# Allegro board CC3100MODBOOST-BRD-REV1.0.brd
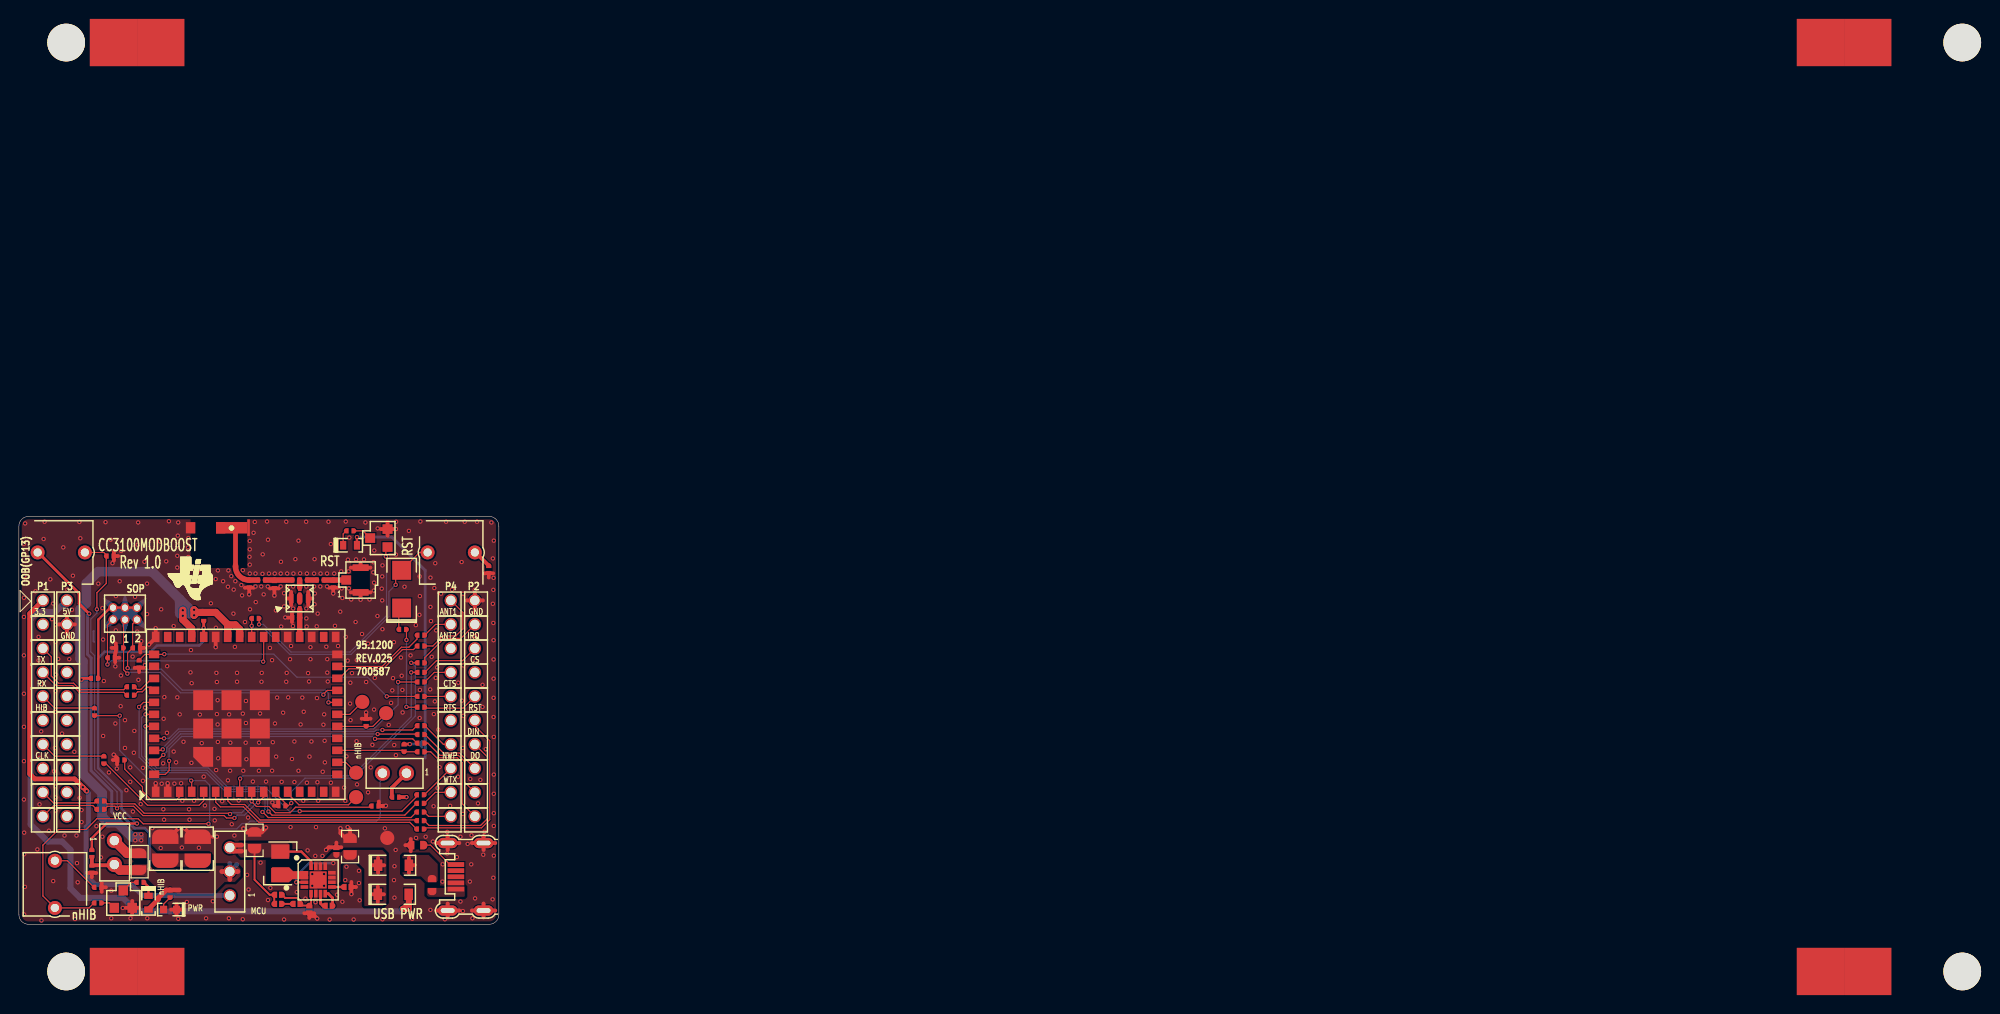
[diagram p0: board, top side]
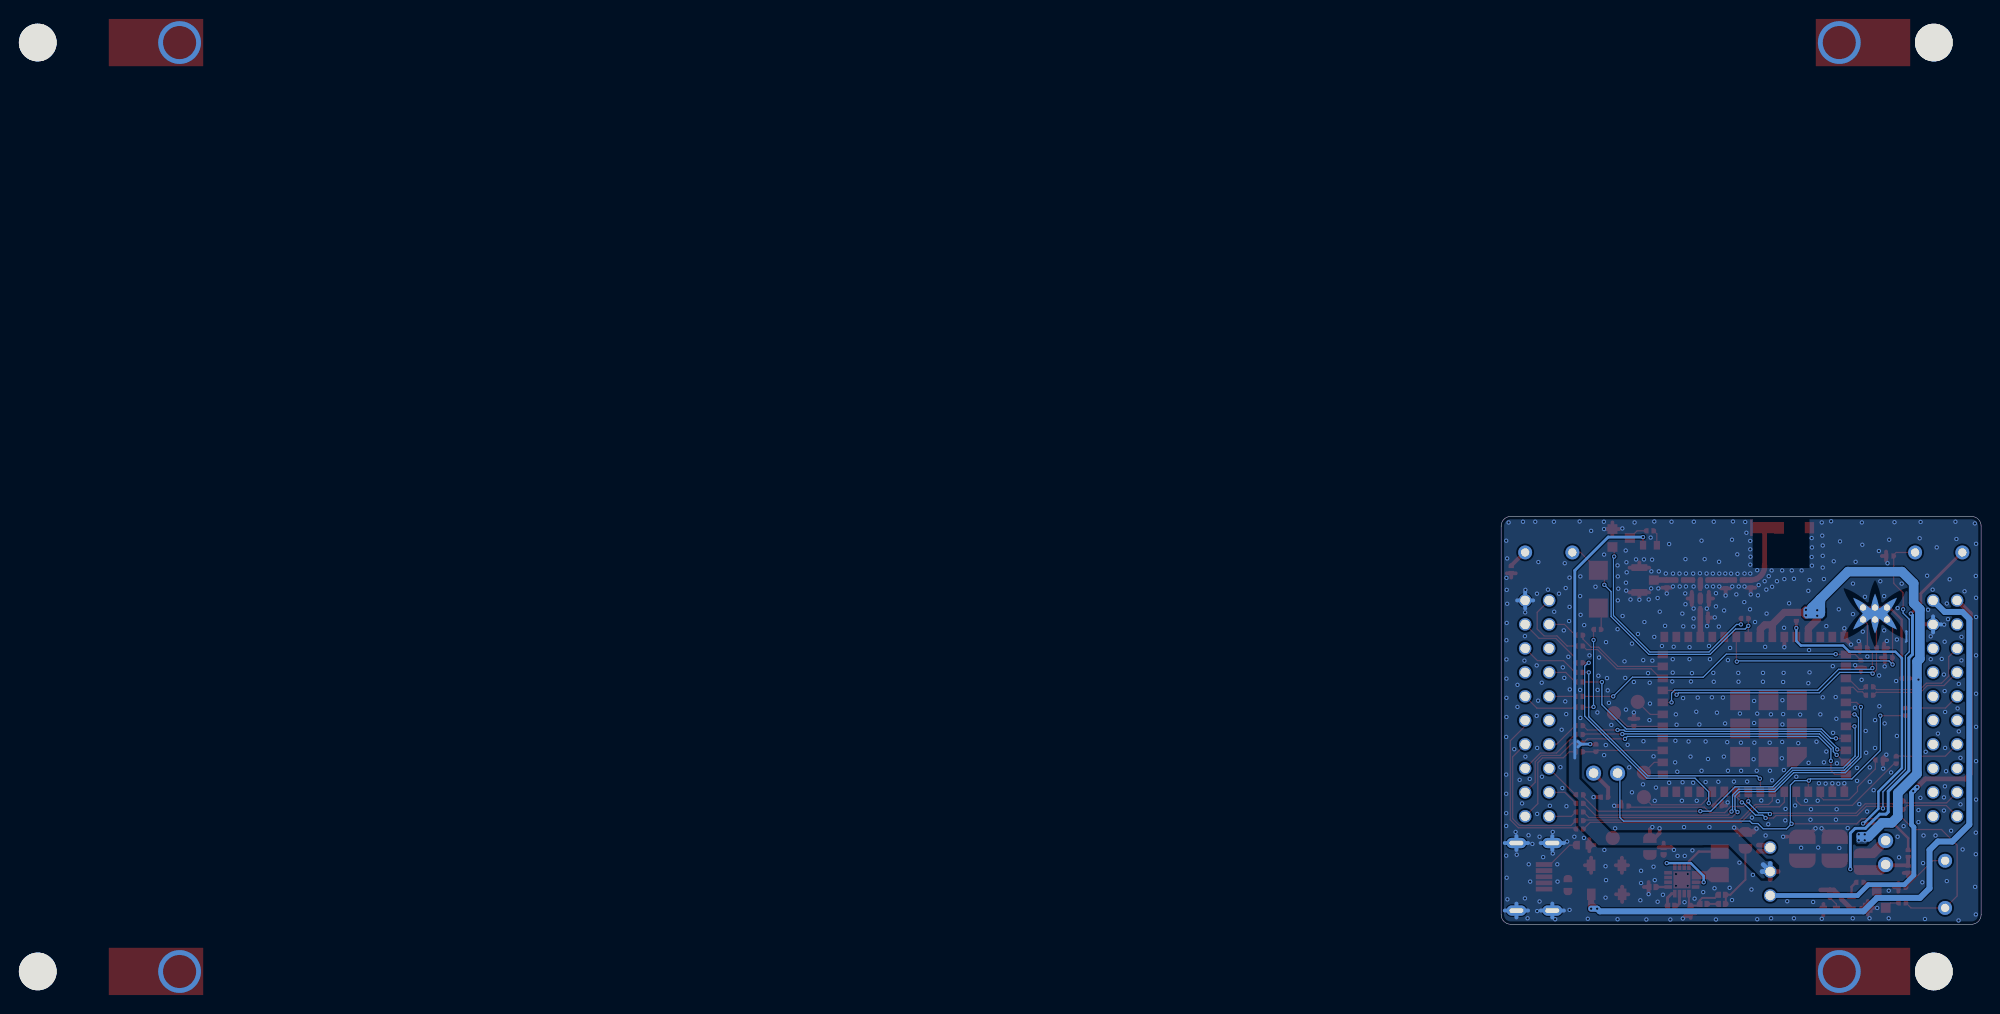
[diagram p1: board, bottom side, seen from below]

Outline 50.8 x 43.18 mm; copper layers: TOP, BOTTOM. Coordinates in mm from the lower left corner of the outline.
Outline path: 0,42.16 0,1.02 arc(0.3,0.3) 1.02,0 49.78,0 arc(50.5,0.3) 50.8,1.02 50.8,42.16 arc(50.5,42.88) 49.78,43.18 1.02,43.18 arc(0.3,42.88) 0,42.16

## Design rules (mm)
net group RF-50: nets N16994724 N16994729 N16994739 N17016892

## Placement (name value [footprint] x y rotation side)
ANT1  2.4GHz  [ANT-T77H533_00C]  19.77 41.98 0 top
C3  10nF  [YT-C-0402]  32.79 1.96 270 top
C4  22uF  [C-0805]  24.94 8.89 180 top
C7  10nF  [YT-C-0402]  34.79 3.95 90 top
C15  0.1uF  [YT-C-0402]  33.6 7.75 180 top
C17  2.2uF  [C-0805]  35.05 8.23 180 top
C23  22pF  [YT-C-0402]  27.43 3.13 90 top
C47  1uF  [C-0402S0]  7.72 5.84 180 top
C64  1.0pF  [C-0402S0]  24.38 36.04 0 top
C65  100uF  [C-1210]  15.49 8 0 top
C66  100uF  [C-1210]  18.92 8 0 top
C67  10pF  [C-0402S0]  31.9 36.45 270 top
C68  DNP  [C-0402S0]  27.04 35.97 0 top
D1  LED-Y  [LD-0603A]  35.05 40.13 270 top
D3  MBR130T1G  [SOD-123A]  39.65 6.25 270 top
D4  MBR130T1G  [SOD-123A]  39.62 3.17 270 top
D5  LED  [LD-0603S0]  16 1.56 90 top
D6  LED-G  [LD-0603A]  13.72 2.29 180 top
D8  DIODE SCHOTTKY  [M-D-SMAH2_3]  40.51 35.48 0 top
FB17  60R  [L-0603S0]  43.73 4.15 0 top
FB18  60R  [L-0603S0]  42.16 8.38 270 top
J2  CONN_U.FL  [CJ-RF-S3_1X3-3]  36.17 36.45 270 top
J3  MM8030-2610RJ3  [CN-MM8030S0]  29.72 34.49 0 top
J4  DNP  [CN-D3X2-1_27HD]  11.23 32.89 270 top
J5  jumper  [CN-2X1-2_54S0]  39.75 16 180 top
J6  jumper  [CN-2X1-2_54S0]  10.11 7.59 270 top
J7  SUA-160M3B-L2E-TR1  [CJ-USBSUA-160M3B-L2AT]  48.13 5.03 90 top
J8  CON3X1  [CN-3X1-2_54]  22.33 5.59 90 top
J9  Header Male 2x10  [CN-10X2-2_54C]  46.99 22.86 270 bottom
J10  Header Male 2x10  [CN-10X2-2_54C]  3.81 22.86 270 bottom
L1  1uH  [L-S3X3A]  27.66 6.45 0 top
L4  3.6nH  [L-0402S0]  25.68 36.45 90 top
L6  DNP  [L-0402S0]  33.27 36.04 180 top
L9  DNP  [L-0402S0]  29.31 32.47 90 top
NOREF  -  [unnamed]  0 88.35 90 top
NOREF#2  -  [#2]  1.6 0 90 top
NOREF#3  -  [#2]  50.8 1.02 0 top
NOREF#4  -  [#2]  117.86 91.86 90 top
NOREF#5  -  [#2]  92.86 96.86 0 top
NOREF#6  -  [unnamed#3]  210.7 88.35 90 top
NOREF#7  -  [unnamed#4]  210.7 0.01 90 top
NOREF#8  -  [#2]  0 42.16 0 top
NOREF#9  -  [#2]  12.01 -0.5 0 top
NOREF#10  -  [#2]  1.02 43.18 90 top
NOREF#11  -  [#2]  1.02 0 90 top
NOREF#12  -  [#2]  1.02 88.36 90 top
NOREF#13  -  [unnamed#5]  0 0.01 90 top
NOREF#14  -  [#2]  0 42.16 0 top
NOREF#15  -  [#2]  1.02 0 90 top
NOREF#16  -  [#2]  0 1.02 0 top
NOREF#17  -  [#2]  1.02 88.36 90 top
NOREF#18  -  [#2]  5 -10 90 top
Q7  BSS138LT3G  [SOT-23B]  11.05 2.67 270 top
Q8  BSS138LT3G  [SOT-23B]  38.1 40.89 0 top
R4  100k  [R-0402S0]  9.78 28.22 270 top
R5  430K  [YT-C-0402]  29.39 2.16 270 top
R7  100k  [R-0402S0]  10.67 29.26 90 top
R8  10k  [R-0402S0]  12.45 29.26 270 top
R9  1k  [R-0402S0]  8 26.04 270 top
R10  DNP  [R-0402S0]  40.61 31.22 270 top
R12  100R  [R-0402S0]  8.36 3.91 270 top
R13  150K  [YT-C-0402]  30.74 1.57 180 top
R14  100R  [R-0402S0]  49.73 37.57 180 top
R15  0R  [R-0402S0]  7.72 7.49 180 top
R16  DNP  [R-0402S0]  19.56 32.49 0 top
R20  1K  [R-0402S0]  8 22.49 0 top
R21  39K  [YT-C-0402]  27.43 2.16 270 top
R22  0R  [R-0402S0]  8.99 17.4 0 top
R24  DNP  [R-0402S0]  8.64 13.06 90 top
R25  DNP  [R-0402S0]  8.64 12.17 90 top
R26  DNP  [R-0402S0]  42.55 29.46 270 top
R27  DNP  [R-0402S0]  42.55 30.61 270 top
R29  0R  [R-0402S0]  42.55 25.65 270 top
R36  0R  [R-0402S0]  42.55 24.13 270 top
R37  0R  [R-0402S0]  42.55 21.03 270 top
R38  0R  [R-0402S0]  42.49 13.72 270 top
R39  DNP  [R-0402S0]  42.49 12.8 270 top
R40  DNP  [R-0402S0]  42.49 11.89 270 top
R44  0R  [R-0402S0]  42.55 27.69 90 top
R46  0R  [R-0402S0]  42.55 26.67 90 top
R48  0R  [R-0402S0]  42.55 22.99 90 top
R65  0R  [R-0402S0]  42.49 10.08 90 top
R66  0R  [R-0402S0]  42.49 10.97 90 top
R67  DNP  [R-0402S0]  42.55 20.09 90 top
R68  DNP  [R-0402S0]  42.55 19.18 90 top
R71  270  [R-0402S0]  12.83 4.45 90 top
R72  270  [R-0402S0]  35.05 41.66 270 top
R73  0R  [R-0402S0]  29.31 36.45 90 top
R74  DNP  [R-0402S0]  30.12 36.45 90 top
R75  DNP  [R-0402S0]  10.79 17.4 270 top
R76  DNP  [R-0201S1]  29.72 35.2 0 top
R77  33k  [R-0402S0]  9.65 38.99 270 top
R78  3.3K  [R-0402S0]  27.84 12.55 90 top
R79  DNP  [R-0201S1]  29.72 33.78 180 top
R81  0R  [R-0402S0]  11.81 25.15 90 top
R82  0R  [R-0402S0]  11.81 24.26 90 top
R83  DNP  [R-0402S0]  42.55 18.26 90 top
R84  33k  [R-0402S0]  37.69 12.52 270 top
R94  DNP  [R-0805]  12.78 6.63 0 top
R111  DNP  [R-0402S0]  40.77 18.67 0 top
R112  100K  [R-0402S0]  36.75 21.36 180 top
R113  100K  [R-0402S0]  12.73 27.56 0 top
R114  10K  [R-0402S0]  39.88 13.46 270 top
R205  330R  [R-0402S0]  16 3.23 180 top
R209  10k  [R-0402S0]  8.36 2.26 270 top
R210  10k  [R-0402S0]  25.02 32.38 270 top
SW1  1BT002-0120L  [SW-D6_2X6_2-2]  4.49 39.37 180 top
SW2  1BT002-0120L  [SW-D6_2X6_2-2]  45.76 39.37 180 top
SW3  1BT002-0120L  [SW-D6_2X6_2-2]  3.81 4.23 270 top
TP1  TP SMD  [ICT059]  38.99 9.14 0 top
TP2  TP SMD  [ICT059]  35.69 13.46 0 top
TP3  TP SMD  [ICT059]  35.69 16.05 0 top
TP4  TP SMD  [ICT059]  38.86 22.35 0 top
TP5  TP SMD  [ICT059]  36.35 23.55 0 top
U1  TLV62090  [TQFN-3X3-16ESHS2]  31.67 4.7 270 top
U11  TI CC3100 module  [E-PMODULE-S20_5X17_5-54S]  24 22.23 0 top

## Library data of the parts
ANT1 = ANT-T77H533_00C
C3 C7 C15 C23 R5 R13 R21 = YT-C-0402
C4 C17 = C-0805
C47 C64 C67 C68 = C-0402S0
C65 C66 = C-1210
D1 D6 = LD-0603A
D3 D4 = SOD-123A
D5 = LD-0603S0
D8 = M-D-SMAH2_3
FB17 FB18 = L-0603S0
J2 = CJ-RF-S3_1X3-3
J3 = CN-MM8030S0
J4 = CN-D3X2-1_27HD
J5 J6 = CN-2X1-2_54S0
J7 = CJ-USBSUA-160M3B-L2AT
J8 = CN-3X1-2_54
J9 J10 = CN-10X2-2_54C
L1 = L-S3X3A
L4 L6 L9 = L-0402S0
Q7 Q8 = SOT-23B
R4 R7-R10 R12 R14-R16 R20 R22 R24-R27 R29 R36-R40 R44 R46 R48 R65-R68 R71-R75 R77 R78 R81-R84 R111-R114 R205 R209 R210 = R-0402S0
R76 R79 = R-0201S1
R94 = R-0805
SW1-SW3 = SW-D6_2X6_2-2
TP1-TP5 = ICT059
U1 = TQFN-3X3-16ESHS2
U11 = E-PMODULE-S20_5X17_5-54S

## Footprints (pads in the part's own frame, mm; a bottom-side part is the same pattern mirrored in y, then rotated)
ANT-T77H533_00C
  rect 0.406x0.406 smd: 1(3.163,-4.005)
  rect 0.991x1.194 smd: 2(1.595,0) 3(-1.595,0)
C-0402S0
  custom 0.127x0.127 smd: 1(0,-0.406) 2(0,0.406)
C-0805
  custom 0.254x0.254 smd: 1(0,-0.889) 2(0,0.889)
C-1210
  custom 0.381x0.381 smd: 1(0,-1.27) 2(0,1.27)
CJ-RF-S3_1X3-3
  rect 0.991x1.041 smd: 1(0,-1.524)
  rect 0.711x1.702 smd: 2(1.311,0) 3(-1.311,0)
CJ-USBSUA-160M3B-L2AT
  rect 0.508x1.753 smd: 1(-1.3,1.877) 2(-0.65,1.877) 3(0,1.877) 4(0.65,1.877) 5(1.3,1.877)
  oval 1.092x2.083 hole 0.483x1.473: S1(3.575,-1.05) S2(-3.575,-1.05) S3(3.575,2.75) S4(-3.575,2.75)
CN-2X1-2_54S0
  round 1.6 hole 0.991: 1(-1.27,0) 2(1.27,0)
CN-3X1-2_54
  round 1.321 hole 0.991: 1(-2.54,0) 2(0,0) 3(2.54,0)
CN-10X2-2_54C
  round 1.321 hole 0.991: 1(-11.43,-1.27) 2(-11.43,1.27) 3(-8.89,-1.27) 4(-8.89,1.27) 5(-6.35,-1.27) 6(-6.35,1.27) 7(-3.81,-1.27) 8(-3.81,1.27) 9(-1.27,-1.27) 10(-1.27,1.27) 11(1.27,-1.27) 12(1.27,1.27) 13(3.81,-1.27) 14(3.81,1.27) 15(6.35,-1.27) 16(6.35,1.27) 17(8.89,-1.27) 18(8.89,1.27) 19(11.43,-1.27) 20(11.43,1.27)
CN-D3X2-1_27HD
  round 0.965 hole 0.66: 1(0.635,-1.27) 2(-0.635,-1.27) 3(0.635,0) 4(-0.635,0) 5(0.635,1.27) 6(-0.635,1.27)
CN-MM8030S0
  rect 0.356x0.356 smd: 1(0,-0.978) 4(0,0.978)
  rect 0.508x1.016 smd: 2(-0.904,0) 3(0.904,0)
E-PMODULE-S20_5X17_5-54S
  rect 0.813x1.092 smd: 1(-9.525,-8.196) 2(-8.255,-8.196) 3(-6.985,-8.196) 4(-5.715,-8.196) 5(-4.445,-8.196) 6(-3.175,-8.196) 7(-1.905,-8.196) 8(-0.635,-8.196) 9(0.635,-8.196) 10(1.905,-8.196) 11(3.175,-8.196) 12(4.445,-8.196) 13(5.715,-8.196) 14(6.985,-8.196) 15(8.255,-8.196) 16(9.525,-8.196) 28(9.525,8.196) 29(8.255,8.196) 30(6.985,8.196) 31(5.715,8.196) 32(4.445,8.196) 33(3.175,8.196) 34(1.905,8.196) 35(0.635,8.196) 36(-0.635,8.196) 37(-1.905,8.196) 38(-3.175,8.196) 39(-4.445,8.196) 40(-5.715,8.196) 41(-6.985,8.196) 42(-8.255,8.196) 43(-9.525,8.196)
  rect 1.092x0.813 smd: 17(9.696,-6.35) 18(9.696,-5.08) 19(9.696,-3.81) 20(9.696,-2.54) 21(9.696,-1.27) 22(9.696,0) 23(9.696,1.27) 24(9.696,2.54) 25(9.696,3.81) 26(9.696,5.08) 27(9.696,6.35) 44(-9.696,6.35) 45(-9.696,5.08) 46(-9.696,3.81) 47(-9.696,2.54) 48(-9.696,1.27) 49(-9.696,0) 50(-9.696,-1.27) 51(-9.696,-2.54) 52(-9.696,-3.81) 53(-9.696,-5.08) 54(-9.696,-6.35)
  custom 0.527x0.527 smd: 55(-4.5,-4.5)
  rect 2.108x2.108 smd: 56(-1.5,-4.5) 57(1.5,-4.5) 58(-4.5,-1.5) 59(-1.5,-1.5) 60(1.5,-1.5) 61(-4.5,1.5) 62(-1.5,1.5) 63(1.5,1.5)
ICT059
  round 1.499 smd: 1(0,0)
L-0402S0
  custom 0.127x0.127 smd: 1(0,-0.406) 2(0,0.406)
L-0603S0
  custom 0.191x0.191 smd: 1(0,-0.686) 2(0,0.686)
L-S3X3A
  rect 1.905x1.524 smd: 1(0,-1.246) 2(0,1.246)
LD-0603A
  rect 0.914x0.66 smd: 1(0,0.728) 2(0,-0.728)
LD-0603S0
  rect 0.813x0.762 smd: 1(0,0.686) 2(0,-0.686)
M-D-SMAH2_3
  rect 2.007x2.007 smd: 1(0,1.999) 2(0,-1.999)
R-0201S1
  custom 0.076x0.076 smd: 1(0,-0.229) 2(0,0.229)
R-0402S0
  custom 0.127x0.127 smd: 1(0,-0.406) 2(0,0.406)
R-0805
  custom 0.254x0.254 smd: 1(0,-0.889) 2(0,0.889)
SOD-123A
  rect 1.219x0.914 smd: 1(0,-1.633) 2(0,1.633)
SOT-23B
  rect 1.067x1.016 smd: 1(0.92,-0.951) 2(0.92,0.951) 3(-0.921,0)
SW-D6_2X6_2-2
  round 1.473 hole 0.864: T1(-2.5,0) T2(2.5,0)
TQFN-3X3-16ESHS2
  rect 0.381x0.813 smd: 1(-0.75,-1.455) 2(-0.25,-1.455) 3(0.25,-1.455) 4(0.75,-1.455) 9(0.75,1.455) 10(0.25,1.455) 11(-0.25,1.455) 12(-0.75,1.455)
  rect 0.813x0.381 smd: 5(1.455,-0.75) 6(1.455,-0.25) 7(1.455,0.25) 8(1.455,0.75) 13(-1.455,0.75) 14(-1.455,0.25) 15(-1.455,-0.25) 16(-1.455,-0.75)
  rect 1.803x1.803 smd: 17(0,0)
unnamed
  round 3.988 hole 3.988 unplated: (5.004,-5.004)
  rect 5.004x5.004 smd: (5.004,-10.008) (5.004,-15.011)
  round 1.016 smd: (5.004,-15.011) 1(5.004,-10.008)
unnamed#3
  round 1.016 smd: (5.006,20.018) 1(5.006,15.014)
  rect 5.004x5.004 smd: (5.006,20.018) (5.006,15.014)
  round 3.988 hole 3.988 unplated: (5.006,5.006)
unnamed#4
  round 1.016 smd: (-5.001,20.018) 1(-5.001,15.014)
  rect 5.004x5.004 smd: (-5.001,20.018) (-5.001,15.014)
  round 3.988 hole 3.988 unplated: (-5.001,5.006)
unnamed#5
  round 3.988 hole 3.988 unplated: (-5.004,-5.004)
  rect 5.004x5.004 smd: (-5.004,-10.008) (-5.004,-15.011)
  round 1.016 smd: (-5.004,-15.011) 1(-5.004,-10.008)
YT-C-0402
  custom 0.153x0.153 smd: 1(0,-0.406) 2(0,0.406)

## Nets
GND: ANT1.2 ANT1.3 C4.1 C7.1 C15.1 C17.1 C47.2 C64.1 C65.2 C66.2 C68.1 D5.2 FB18.1 J2.2 J2.3 J3.2 J3.3 J7.S1 J7.S2 J7.S3 J7.S4 J9.1 J10.3 L6.2 L9.2 Q7.2 Q8.2 R4.2 R7.2 R8.2 R12.2 R13.2 R14.2 R75.1 R77.2 R78.2 R84.2 R112.1 R113.1 TP1.1 U1.6 U1.14 U1.15 U1.17 U11.1 U11.2 U11.16 U11.27 U11.28 U11.30 U11.32 U11.38 U11.43 U11.55 U11.56 U11.57 U11.58 U11.59 U11.60 U11.61 U11.62 U11.63
VCC_3V3: C47.1 D1.1 D6.1 J6.2 J8.2 R15.2 R94.1 R111.2 R114.2 R205.1 SW1.T2
VCC_5V: C15.2 C17.2 D3.1 D4.1 U1.3 U1.10 U1.11 U1.12 U1.13
VCC_HOST_3V3: J8.1 J10.2
VCC_MCU_5V: D4.2 J10.1
VDD_FLASH: R15.1 R16.1 U11.39
ANT_SEL_1: R26.1 U11.25
ANT_SEL_2: R27.1 U11.26
CC_GPIO08: R67.2 U11.53
CC_GPIO09: R68.2 U11.54
CC_GPIO12: R24.1 R84.1 U11.9
CC_GPIO13: R25.1 R77.1 SW1.T1 U11.10
CC_IRQ: R44.2 R78.1 U11.11
CC_MODESEL: R83.2 R111.1 U11.19
CC_NHIB: J5.2 R20.1 R209.1 SW3.T2 U11.4
CC_NWP_UART_TX: R37.1 U11.52
CC_SPI_CLK: R22.1 U11.5
CC_SPI_CS: R46.2 U11.8
CC_SPI_DIN: R65.2 U11.6
CC_SPI_DOUT: R66.2 U11.7
CC_UART1_CTS: R29.1 U11.51
CC_UART1_RTS: R36.1 R113.2 U11.44
CC_UART1_RX: R82.1 U11.47
CC_UART1_TX: R81.1 U11.46
CC_VBAT: C65.1 C66.1 J6.1 R9.1 R16.2 R94.2 U11.36 U11.37 U11.40
CC_WL_RS232_RX: R39.1 U11.49
CC_WL_RS232_TX: R40.1 U11.48
CC_WL_UART_TX: R38.1 U11.50
MCU_RESET: R10.2 R48.2
REG_3V3: C4.2 C23.2 J8.3 L1.2 R21.1 U1.16
RESET_N: D8.1 R210.1 SW2.T2 U11.35
SOP0: J4.1 R4.1 U11.34
SOP1: J4.3 R7.1 U11.24
SOP2/TCXO_EN: J4.5 R8.1 U11.23
N16764527: J10.6 R81.2
N16764535: J10.8 R82.2
N16791492: R75.2 U11.3
N16793910: J3.1 L9.1 R79.2 U11.31
N16834605: J10.10 R20.2
N16837569: J4.2 J4.4 J4.6 R9.2
N16839855: J10.14 R22.2
N16840001: J10.18 R24.2
N16840004: J10.20 R25.2
N16841033: J9.2 R26.2
N16841054: J9.4 R27.2
N16841184: J9.8 R29.2
N16841224: J9.10 R36.2
N16841243: J9.14 R37.2
N16841270: J9.16 R38.2
N16841340: J9.18 R39.2
N16841345: J9.20 R40.2
N16842182: J9.3 R44.1
N16842199: J9.5 R46.1
N16842274: J9.9 R48.1
N16842295: J9.11 R65.1
N16842317: J9.13 R66.1
N16842351: J9.15 R67.1
N16842362: J9.17 R68.1
N16842381: J9.19 R83.1
N16884236: D8.2 R10.1
N16888596: FB17.1 J7.1
N16892431: D5.1 R205.2
N16917012: D3.2 FB17.2
N16970552: C7.2 U1.9
N16970558: C23.1 R5.2 R13.1 U1.5
N16970663: C3.1 U1.7
N16970665: C3.2 U1.8
N16970679: L1.1 U1.1 U1.2
N16970748: R5.1 R21.2
N16976507: Q7.1 R209.2
N16976519: D6.2 R71.1
N16976522: Q7.3 R71.2
N16976578: D1.2 R72.1
N16976580: Q8.3 R72.2
N16976712: Q8.1 R210.2
N16994679: J3.4 R73.1 R74.2 R76.2
N16994724: C67.1 R74.1
N16994729: C67.2 J2.1 L6.1
N16994739: C68.2 L4.1 R73.2
N17016892: ANT1.1 C64.2 L4.2
N17029182: R76.1 R79.1
N17031765: R12.1 SW3.T1
N17035781: J5.1 R114.1
N17040721: R112.2 TP4.1 U11.21
N17042673: R14.1 SW2.T1
N17042921: FB18.2 J7.5
N17042983: TP2.1 U11.12
N17042994: TP3.1 U11.18
N17043038: TP5.1 U11.22

Pads without a net: J7 2 3 4; J9 6 7 12; J10 4 5 7 9 11 12 13 15 16 17 19; NOREF 1; NOREF#6 1; NOREF#7 1; NOREF#13 1; U1 4; U11 13 14 15 17 20 29 33 41 42 45

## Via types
v1: diameter 0.457, hole 0.254, TOP to BOTTOM, 592 vias
v2: diameter 0.254, hole 0.254, TOP to BOTTOM, 4 vias

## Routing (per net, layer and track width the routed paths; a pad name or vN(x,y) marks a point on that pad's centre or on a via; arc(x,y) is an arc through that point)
GND: length 108.9
  TOP w0.406: v1(16.89,10.16) 16,9.27 C65.2 ; v1(32.51,7.87) 32.79,8.15 C15.1 ; R77.2 10.5,38.99 ; R77.2 10.06,38.52 ; R77.2 10.06,39.46 ; 12.85,28.79 R8.2 ; R8.2 13.3,29.26 ; R8.2 12.85,29.73 ; 49.73,36.71 R14.2 ; R14.2 49.26,37.16 ; R14.2 50.2,37.16 ; C7.1 35.69,3.95 ; C7.1 v1(35.19,3.19) ; C7.1 35.19,4.47 ; R13.2 31.26,1.17 ; R13.2 30.74,0.67 ; R13.2 30.22,1.17 ; R13.2 31.02,0.89 31.29,0.89 v1(31.57,0.61) ; J7.S3 45.38,9.34 ; J7.S3 45.38,7.87 ; J7.S3 46.62,8.6 ; J7.S3 44.15,8.6 ; 7.72,4.99 C47.2 ; C47.2 7.25,5.44 ; C47.2 8.19,5.44 ; 35.13,35.14 J2.2 ; J2.2 36.17,34.59 ; J2.2 37.21,35.14 ; J9.1 49.11,34.29 ; J9.1 48.26,33.44 ; J9.1 47.41,34.29 ; J9.1 48.26,35.14 ; v1(17.53,10.16) 18.41,9.27 C66.2 ; R12.2 8.76,4.38 ; R12.2 9.21,3.91 ; R12.2 8.76,3.44 ; 11.3,1.75 Q7.2 ; Q7.2 12.7,1.75 ; Q7.2 12,1.02 ; Q7.2 12,2.47 ; L6.2 33.75,35.64 ; L6.2 v1(33.27,35.03) ; L6.2 32.8,35.64 ; 45.38,0.72 J7.S4 ; J7.S4 45.38,2.19 ; J7.S4 46.62,1.45 ; J7.S4 44.15,1.45 ; J3.2 28.81,35.19 ; J3.2 28.37,34.49 ; J3.2 28.81,33.79 ; v1(10.03,17.96) 10.39,17.6 R75.1 ; J10.3 5.93,31.75 ; J10.3 4.23,31.75 ; J10.3 5.08,32.6 ; J10.3 5.08,30.9 ; 39.02,41.15 Q8.2 ; Q8.2 v1(39.91,41.84) ; Q8.2 39.02,42.54 ; Q8.2 38.3,41.84 ; J7.S1 50.42,8.6 ; J7.S1 47.95,8.6 ; J7.S1 49.18,7.87 ; J7.S1 49.18,9.34 ; 28.91,32 L9.2 ; L9.2 28.91,32.94 ; L9.2 28.46,32.47 ; U11.2 v1(15.75,14.93) ; C15.1 33.6,8.65 ; C15.1 34.13,8.15 ; J3.3 30.62,35.19 ; J3.3 31.07,34.49 ; J3.3 30.62,33.79 ; U11.1 v1(14.48,14.93) ; R84.2 v1(38.84,12.55) ; R84.2 38.1,12.99 ; R84.2 38.55,12.52 ; v1(34.04,10.16) 34.04,9.65 34.57,9.12 C17.1 35.05,10.03 v1(34.8,10.29) ; 49.18,0.72 J7.S2 ; J7.S2 50.42,1.45 ; J7.S2 47.95,1.45 ; J7.S2 49.18,2.19 ; 9.82,29.26 R7.2 ; R7.2 10.26,28.79 ; R7.2 10.26,29.73 ; R113.1 13.2,27.15 ; R113.1 12.25,27.15 ; R113.1 12.73,26.71 ; C68.1 v1(27.04,34.81) ; C68.1 27.52,35.56 ; C68.1 26.57,35.56 ; 10.39,16.93 R75.1 ; R75.1 9.94,17.4 ; 20.51,9.27 v1(20.95,9.27) ; R4.2 10.63,28.22 ; R4.2 10.19,28.69 ; R4.2 10.19,27.75 ; 16.69,0.96 D5.2 ; D5.2 17.26,1.56 ; D5.2 16.69,2.15 ; D5.2 16.12,1.56 ; 40.91,8.38 FB18.1 ; FB18.1 41.48,9.03 ; FB18.1 41.48,7.73 ; R112.1 v1(36.75,22.43) ; R112.1 37.23,21.77 ; R112.1 36.28,21.77 ; U11.38 v1(20.83,29.34) ; v1(14.48,31.34) U11.43 14.48,30.33 v1(13.77,29.62) ; 35.13,37.76 J2.3 ; J2.3 37.21,37.76 ; J2.3 36.17,38.31 ; 27.43,13.02 R78.2 26.99,12.55 ; C64.1 v1(24.38,34.92) ; C64.1 23.91,35.64 ; C64.1 24.85,35.64
  TOP w0.508: v1(26.14,10.24) 25.68,9.78 C4.1 24.13,9.78 v1(23.77,10.13)
  BOTTOM w0.203: 7.92,31.04 7.9,31.01 7.9,29.97 7.98,29.9
  BOTTOM w0.406: 47.95,8.6 J7.S1 ; J7.S1 50.42,8.6 ; J7.S1 49.18,7.87 ; J7.S1 49.18,9.34 ; J7.S3 46.62,8.6 ; J7.S3 45.38,7.87 ; J7.S3 44.15,8.6 ; J7.S3 45.38,9.34 ; J10.3 5.08,32.6 ; J10.3 4.23,31.75 ; J10.3 5.08,30.9 ; J7.S4 45.38,2.19 ; J7.S4 45.38,0.72 ; J7.S4 46.62,1.45 ; J7.S4 44.15,1.45 ; J9.1 48.26,35.14 ; J9.1 48.26,33.44 ; J9.1 49.11,34.29 ; J9.1 47.41,34.29 ; J7.S2 50.42,1.45 ; J7.S2 49.18,2.19 ; J7.S2 49.18,0.72 ; J7.S2 47.95,1.45
  vias: v1(0.53,40.28) v1(0.53,34.57) v1(0.53,32.54) v1(0.53,28.47) v1(0.53,24.41) v1(0.53,20.9) v1(0.53,17.27) v1(0.53,13.21) v1(0.56,36.88) v1(0.56,9.7) v1(0.56,7.42) v1(0.64,3.96) v1(0.56,1.04) v1(0.66,42.44) v1(1.75,35.26) v1(1.96,7.92) v1(2.08,30.43) v1(2.08,27.94) v1(2.18,17.63) v1(2.18,12.7) v1(2.36,25.45) v1(2.36,20.42) v1(2.39,0.41) v1(2.49,22.86) v1(2.62,40.79) v1(2.72,42.62) v1(3.17,9.91) v1(3.33,36.53) v1(3.51,32.31) v1(3.63,33.96) v1(3.63,4.57) v1(3.71,16.21) v1(3.81,22.48) v1(3.81,18.67) v1(3.84,14.61) v1(3.91,31.72) v1(3.86,29.92) v1(3.94,26.44) v1(3.86,24.69) v1(3.94,13.44) v1(3.94,12.04) v1(4.17,28.09) v1(4.57,20.19) v1(4.7,39.9) v1(4.83,9.4) v1(5.13,35.43) v1(5.33,30.48) v1(5.33,28.07) v1(5.61,33.3) v1(5.71,36.91) v1(5.87,18.26) v1(5.94,0.56) v1(6.1,9.4) v1(6.15,6.48) v1(6.22,4.45) v1(6.4,42.6) v1(6.43,13.39) v1(6.5,40.87) v1(6.63,12.09) v1(6.63,10.82) v1(8.2,10.39) v1(8.41,36.07) v1(8.69,7.09) v1(8.84,33.48) v1(8.84,9.27) v1(8.92,30.15) v1(8.92,19.94) v1(8.99,25.76) v1(9.17,42.57) v1(9.53,16.08) v1(9.73,40.72) v1(9.78,3.56) v1(9.78,0.63) v1(9.91,38.23) v1(9.98,30) v1(10.21,27.3) v1(10.21,21.26) v1(10.26,34.75) v1(10.26,31.12) v1(10.36,16.48) v1(10.67,36.32) v1(10.82,39.52) v1(10.79,26.34) v1(10.77,23.09) v1(11,1.73) v1(11.23,21.62) v1(11.23,18.67) v1(11.38,14.2) v1(11.79,16.61) v1(11.79,15.09) v1(11.81,0.63) v1(12.04,28.35) v1(12.06,11.94) v1(12.22,20.47) v1(12.17,18.16) v1(12.29,34.67) v1(12.52,30.99) v1(12.62,42.55) v1(12.57,40.18) v1(12.65,25.88) v1(12.89,12.73) v1(12.95,29.97) v1(13.13,16.56) v1(13.13,15.19) v1(13.28,38.38) v1(13.34,27.43) v1(13.36,22.94) v1(13.56,36.07) v1(13.56,32.84) v1(13.59,0.63) v1(14.12,10.19) v1(14.94,40.54) v1(15.01,8.08) v1(15.06,33.35) v1(15.11,14.88) v1(15.32,21.76) v1(15.27,17.04) v1(15.29,12.18) v1(15.39,24.05) v1(15.37,11.07) v1(15.6,38.43) v1(15.7,27.33) v1(15.67,20.27) v1(15.88,42.67) v1(16.38,31.57) v1(16.38,18.29) v1(16.46,14.9) v1(16.64,36.55) v1(16.64,17.14) v1(16.81,41.15) v1(16.76,40.11) v1(16.76,39.01) v1(16.76,37.77) v1(16.76,24.03) v1(16.87,42.55) v1(16.87,0.58) v1(17.02,22.23) v1(17.17,14.93) v1(17.25,8.13) v1(17.3,13.08) v1(17.42,19.33) v1(17.78,2.36) v1(17.93,40.89) v1(17.91,39.9) v1(17.93,38.89) v1(17.91,37.97) v1(18.01,12.18) v1(18.06,11.07) v1(18.16,36.45) v1(18.21,29.03) v1(18.16,26.67) v1(18.29,35.31) v1(18.29,25.53) v1(18.26,17.09) v1(18.54,13.08) v1(19,37.47) v1(19.05,8.1) v1(19.15,22.2) v1(19.35,19.18) v1(19.56,15.63) v1(19.68,12.57) v1(19.81,36.58) v1(19.81,0.63) v1(20.04,37.47) v1(20.32,33.99) v1(20.52,2.44) v1(20.7,12.22) v1(20.73,11) v1(20.83,36.55) v1(20.85,31.39) v1(20.9,26.62) v1(20.88,16.33) v1(20.95,25.65) v1(21.03,23.72) v1(20.95,22.25) v1(21.03,21.16) v1(21.06,37.47) v1(21.06,19.3) v1(21.09,17.58) v1(21.51,13.03) v1(21.62,36.32) v1(22.12,35.74) v1(22.12,15.24) v1(22.17,37.47) v1(22.23,0.63) v1(22.25,22.23) v1(22.38,19.23) v1(22.35,16.26) v1(22.48,36.86) v1(22.53,10.59) v1(22.73,35.43) v1(22.71,32.89) v1(22.81,9.4) v1(22.91,36.32) v1(22.86,29.38) v1(23.09,26.62) v1(23.09,25.68) v1(23.27,13.11) v1(23.55,35.92) v1(23.62,34.82) v1(23.7,37.49) v1(23.7,22.3) v1(23.75,16.26) v1(23.7,0.53) v1(23.93,32) v1(24.03,23.65) v1(24.03,21.31) v1(24,19.23) v1(24.08,17.48) v1(24.16,5.23) v1(24.26,11.3) v1(24.31,3.68) v1(24.43,40.59) v1(24.43,39.7) v1(24.41,38.91) v1(24.43,38.07) v1(24.43,37.13) v1(24.46,33.35) v1(24.84,41.45) v1(24.77,15.11) v1(24.97,42.6) v1(25.04,37.13) v1(25.04,35.76) v1(25.07,34.11) v1(25.43,19.23) v1(25.4,16.26) v1(25.53,22.32) v1(25.58,6.53) v1(25.65,35.76) v1(25.7,26.62) v1(25.68,25.68) v1(25.81,39.17) v1(25.78,37.11) v1(25.91,34.92) v1(26.16,15.11) v1(26.26,42.65) v1(26.34,35.76) v1(26.37,40.72) v1(26.37,2.57) v1(26.47,37.13) v1(26.57,29.26) v1(26.62,3.86) v1(26.8,27.97) v1(26.8,16.26) v1(26.83,12.9) v1(26.87,19.28) v1(27.08,37.13) v1(27.1,21.26) v1(27.2,33.22) v1(27.23,17.75) v1(27.33,24) v1(27.74,38.38) v1(27.71,37.13) v1(27.71,35.76) v1(27.76,31.52) v1(27.81,15.09) v1(27.97,22.4) v1(28.07,35.05) v1(28.07,33.66) v1(28.07,0.51) v1(28.19,32.49) v1(28.22,3.81) v1(28.3,42.62) v1(28.35,26.62) v1(28.3,25.68) v1(28.4,37.13) v1(28.37,35.76) v1(28.5,24.03) v1(28.7,28.07) v1(28.8,29.46) v1(28.75,10.29) v1(28.91,17.5) v1(29.03,35.76) v1(29.03,33.43) v1(29.01,31.57) v1(29.06,37.13) v1(29.16,19.35) v1(29.16,15.06) v1(29.26,38.66) v1(29.41,3.4) v1(29.59,40.61) v1(29.59,16.26) v1(29.77,37.16) v1(29.82,21.16) v1(30,24) v1(30.15,22.5) v1(30.1,13.08) v1(30.33,2.72) v1(30.4,42.62) v1(30.43,35.76) v1(30.43,33.43) v1(30.43,32.38) v1(30.48,37.13) v1(30.45,31.52) v1(30.48,14.99) v1(30.61,26.59) v1(30.56,7.82) v1(30.71,25.7) v1(30.76,17.75) v1(30.86,29.34) v1(30.86,28.07) v1(30.96,19.35) v1(31.24,37.13) v1(31.24,35.76) v1(31.29,38.66) v1(31.32,35.03) v1(31.29,33.88) v1(31.45,10.29) v1(31.37,7.24) v1(31.39,2.34) v1(31.52,31.55) v1(31.55,23.95) v1(31.62,32.89) v1(31.6,15.04) v1(31.67,13.08) v1(31.93,37.13) v1(31.9,35.76) v1(32.13,7.24) v1(32.23,21.13) v1(32.16,16.15) v1(32.31,22.23) v1(32.36,19.43) v1(32.38,17.14) v1(32.54,29.39) v1(32.61,37.13) v1(32.61,35.76) v1(32.64,28.07) v1(32.64,26.64) v1(32.69,25.7) v1(32.77,42.62) v1(32.89,0.51) v1(33.02,40.26) v1(33.02,14.99) v1(33.38,37.13) v1(33.45,31.6) v1(33.68,3.12) v1(33.78,29.46) v1(34.01,33.1) v1(34.11,37.36) v1(34.16,35.56) v1(34.24,34.54) v1(34.24,2.39) v1(34.42,14.48) v1(34.54,13.08) v1(34.54,4.67) v1(34.59,42.65) v1(34.59,30.43) v1(34.67,17.78) v1(34.67,6.1) v1(34.82,38.61) v1(34.8,27.91) v1(34.9,37.36) v1(34.92,35.56) v1(34.98,40.94) v1(35.08,25.58) v1(35.05,23.37) v1(35.1,21.62) v1(35.18,34.39) v1(35.26,26.59) v1(35.43,0.51) v1(35.64,32) v1(35.69,38.63) v1(35.74,19.38) v1(35.76,27.97) v1(35.79,14.81) v1(35.99,5.66) v1(35.99,4.37) v1(36.07,2.54) v1(36.17,34.37) v1(36.32,30.73) v1(36.53,38.63) v1(36.68,42.55) v1(36.75,25.65) v1(36.96,29.72) v1(36.96,13.97) v1(37.11,34.39) v1(37.24,16.61) v1(37.41,19) v1(37.54,38.33) v1(37.52,37.26) v1(37.62,39.57) v1(37.59,36.17) v1(37.57,35.33) v1(37.59,22.73) v1(37.74,27.84) v1(37.67,26.09) v1(37.95,32.64) v1(37.97,41.91) v1(38.4,35.53) v1(38.48,38) v1(38.46,36.83) v1(38.46,34.29) v1(38.48,31.24) v1(38.48,0.53) v1(38.73,10.16) v1(39.14,21.11) v1(39.4,23.44) v1(39.52,24.77) v1(39.6,26.06) v1(39.7,29.87) v1(39.73,18.97) v1(39.7,4.67) v1(39.75,6.15) v1(39.75,2.82) v1(39.93,42.62) v1(39.9,39.14) v1(39.9,17.91) v1(39.88,7.87) v1(40.44,28.24) v1(40.51,26.31) v1(40.59,24.82) v1(40.61,22.43) v1(40.82,35.74) v1(41.27,41.66) v1(41.45,28.47) v1(41.63,0.58) v1(42.01,31.67) v1(42.04,9.14) v1(42.42,36.83) v1(42.44,34.75) v1(42.39,32.77) v1(42.44,24.82) v1(42.42,21.84) v1(42.49,42.65) v1(43.05,9.27) v1(43.54,24.87) v1(43.56,36.7) v1(43.56,33.6) v1(43.61,32.11) v1(43.56,1.52) v1(43.69,28.32) v1(43.81,8.76) v1(43.92,22.25) v1(43.89,12.5) v1(43.97,35.6) v1(44.02,23.6) v1(44.07,38.23) v1(44.12,26.09) v1(44.17,31.12) v1(44.27,27.2) v1(44.32,14.43) v1(44.4,20.6) v1(44.53,16.64) v1(44.68,35) v1(44.83,4.52) v1(44.86,6.35) v1(45.09,0.53) v1(45.21,42.62) v1(45.19,33.1) v1(45.34,9.78) v1(45.34,7.49) v1(45.64,12.55) v1(45.85,35.43) v1(46.35,7.11) v1(46.51,25.58) v1(46.48,15.62) v1(46.74,9.27) v1(46.74,2.41) v1(46.86,38.35) v1(46.89,23.67) v1(47.02,35) v1(47.04,27.41) v1(47.04,22.07) v1(46.99,18.67) v1(46.99,11.68) v1(46.99,1.4) v1(47.19,42.62) v1(47.5,8.51) v1(47.73,4.52) v1(47.78,15.39) v1(47.9,9.42) v1(47.88,6.35) v1(48.01,0.63) v1(48.23,35.41) v1(48.23,17.75) v1(48.26,33.02) v1(48.29,30.51) v1(48.34,27.91) v1(48.29,2.74) v1(48.49,42.62) v1(48.59,12.8) v1(48.84,15.29) v1(49.07,25.35) v1(49.07,23.01) v1(49.15,7.37) v1(49.28,9.78) v1(49.42,18.54) v1(50.01,42.55) v1(50.14,2.64) v1(50.16,38.73) v1(50.24,36.68) v1(50.21,35.41) v1(50.16,33.93) v1(50.21,31.9) v1(50.24,30.07) v1(50.24,28.04) v1(50.24,26.01) v1(50.24,23.98) v1(50.24,21.95) v1(50.22,4.93) v1(50.27,40.61) v1(50.27,19.84) v1(50.27,15.85) v1(50.27,13.82) v1(50.27,11.76) v1(50.27,10.41) v1(50.27,7.26) v2(31.05,5.32) v2(31.05,4.08) v2(32.3,5.32) v2(32.3,4.08)
VCC_3V3: length 88
  TOP w0.254: D1.1 v1(35.78,41)
  TOP w0.305: SW1.T2 2.03,39.37 6.38,35.03 6.38,33.93 7.42,32.89 v1(7.44,32.89) ; R111.2 v1(41.38,19.08)
  TOP w0.406: J6.2 10.03,6.25 C47.1 R15.2 ; R114.2 v1(41.02,13.46)
  TOP w0.508: 16.97,3.63 R205.1 15.6,3.63 14.76,2.79 14.76,2.64 13.72,1.6 D6.1 ; J8.2 21.48,5.59 ; J8.2 22.33,4.74 ; J8.2 23.18,5.59
  TOP w1.016: R94.1 10.69,5.74 J6.2
  BOTTOM w0.305: 42.37,19.08 42.39,19.08 42.67,19.35 ; 42.37,19.08 v1(41.38,19.08) ; 42.37,19.08 42.67,18.77 ; v1(7.44,32.89) 7.26,32.72 7.26,28.57 7.65,28.19 7.65,16.26 9.83,14.07 9.83,11.89 10.06,11.66 10.74,11.66 12.24,10.16 13.34,10.16 13.84,9.65 v1(13.84,5.84) ; 43,17.6 43,37.47 39.47,41 v1(35.78,41)
  BOTTOM w0.508: J8.2 23.18,5.59 ; J8.2 23.06,6.32 ; J8.2 22.33,6.44
VCC_5V: length 11.8
  TOP w0.254: U1.3 v1(29.36,4.45)
  TOP w0.406: 37.34,3.17 D4.1 ; D4.1 37.99,3.98 ; D4.1 37.99,2.37 ; D4.1 38.64,3.17 ; 37.37,6.25 D3.1 ; D3.1 38.02,7.05 ; D3.1 38.66,6.25 ; D3.1 38.02,5.45
  BOTTOM w0.254: v1(29.36,4.45) 29.36,5.11 30.73,6.48 v1(33.27,6.48)
VCC_HOST_3V3: length 51.5
  TOP w0.508: v1(7.18,14.1) 7.11,14.17 7.11,14.17 6.81,14.48 v1(6.77,14.52) 5.89,15.39 1.68,15.39 1.14,15.93 1.14,32.89 J10.2
  BOTTOM w0.508: v1(6.77,14.52) 6.81,14.48 7.11,14.17 7.11,14.17 v1(7.18,14.1) 7.37,13.91 7.37,10.54 7.11,10.29 7.11,5.21 8.13,4.19 11.94,4.19 13.08,3.05 J8.1
VCC_MCU_5V: length 75.6
  TOP w0.635: 41.27,2.16 41.27,3.16 D4.2 ; 41.27,2.16 v1(41.27,1.65) 40.77,1.65 ; 41.27,2.16 40.77,1.65 ; 40.77,1.65 v1(40.64,1.65)
  BOTTOM w0.635: v1(41.27,1.65) v1(40.64,1.65) 40.36,1.37 12.45,1.37 11.02,2.79 6.48,2.79 5.46,3.81 5.46,7.87 4.57,8.76 3.05,8.76 1.24,10.57 1.24,32.33 1.98,33.07 3.86,33.07 J10.1
VDD_FLASH: length 40.8
  TOP w0.254: R15.1 7.72,9.12 9.27,10.67 v1(12.5,10.67)
  TOP w0.305: R16.1 v1(19.56,31.37) U11.39
  BOTTOM w0.254: v1(19.56,31.37) 19.56,30 19.08,29.51 14.61,29.51 13.94,28.85 9.07,28.85 8.38,28.17 8.38,16.54 10.87,14.05 10.87,12.24 12.45,10.67 v1(12.5,10.67)
ANT_SEL_1: length 9.9
  TOP w0.127: U11.25 33.91,26.04 34.92,27.05 38.56,27.05 40.59,29.08 41.76,29.08 R26.1
ANT_SEL_2: length 10
  TOP w0.127: 33.7,27.3 38.46,27.3 40.49,29.34 41.27,29.34 42.14,30.2 R27.1
CC_GPIO08: length 29.3
  TOP w0.127: v1(15.29,17.93) 15.27,17.93 14.48,17.14 14.31,17.14 ; v1(37.97,20.14) 42.09,20.14 R67.2
  BOTTOM w0.127: v1(37.97,20.14) 37.96,20.15 17.11,20.15 15.65,18.7 15.65,18.68 15.65,18.67 15.65,18.29 v1(15.29,17.93)
CC_GPIO09: length 31.1
  TOP w0.127: R68.2 41.68,19.63 v1(37.69,19.63) ; v1(15.9,17.3) 15.9,16.28 15.49,15.88 U11.54
  BOTTOM w0.127: v1(37.69,19.63) 37.43,19.89 17.22,19.89 15.9,18.57 v1(15.9,17.3)
CC_GPIO12: length 31.3
  TOP w0.127: v1(22.35,11.67) 22.27,11.76 13.26,11.76 12.27,12.75 9.35,12.75 R24.1 ; R84.1 37.16,12.4 29.29,12.4 28.7,11.81 27.14,11.81 26.48,12.47 25.15,12.47 24.64,12.98 v1(24.64,13.03) U11.9
  BOTTOM w0.127: v1(22.35,11.67) 22.49,11.81 23.57,11.81 24.64,12.88 v1(24.64,13.03)
CC_GPIO13: length 50.2
  TOP w0.127: U11.10 25.91,13.49 v1(25.32,12.9) ; v1(22.81,11.25) 21.97,11.25 21.72,11.51 13.13,11.51 12.14,12.5 10.62,12.5 v1(10.39,12.27) 10.16,12.5 9.37,12.5 R25.1 ; v1(8.26,33.35) 8.26,35.1 9.25,36.09 R77.1 9.25,39.12 8.99,39.37 SW1.T1
  BOTTOM w0.127: v1(8.26,33.35) 8.26,32.94 7.61,32.3 7.61,28.85 8.01,28.45 8.01,16.4 10.39,14.02 v1(10.39,12.27) ; v1(22.81,11.25) 23.11,11.56 23.88,11.56 25.22,12.9 v1(25.32,12.9)
CC_IRQ: length 26.8
  TOP w0.127: U11.11 27.18,13.84 28.24,12.78 R78.1 28.5,12.55 28.78,12.83 v1(28.83,12.83) ; v1(41.53,27.69) R44.2
  BOTTOM w0.127: v1(41.53,27.69) 41.61,27.69 41.96,27.33 41.96,22.04 35.39,15.47 30.28,15.47 28.83,14.02 v1(28.83,12.83)
CC_MODESEL: length 8.5
  TOP w0.127: R83.2 R111.1 40.61,18.41 U11.19
CC_NHIB: length 76.9
  TOP w0.127: v1(20.07,10.64) 13.16,10.64 12.62,11.18 8.26,11.18 7.11,10.03 4.19,10.03 2.54,8.38 2.54,3 SW3.T2 7.42,1.73 R209.1 ; v1(18.24,15.21) 18.29,15.16 U11.4 ; R20.1 v1(10.67,22.09)
  BOTTOM w0.127: J5.2 38.23,15.75 38.23,11.3 37.85,10.92 24.47,10.92 24.21,10.67 23.62,10.67 23.06,10.11 20.6,10.11 v1(20.07,10.64) 20.19,10.77 20.19,14.73 19.72,15.21 18.24,15.21 v1(18.24,15.21) 18.06,15.39 13.68,15.39 10.67,18.4 v1(10.67,22.09)
CC_NWP_UART_TX: length 29
  TOP w0.127: v1(38.48,20.57) 41.68,20.57 R37.1 ; U11.52 15.13,18.41 v1(15.23,18.52)
  BOTTOM w0.127: v1(15.23,18.52) 15.23,18.66 16.99,20.42 37.66,20.42 37.81,20.57 v1(38.48,20.57)
CC_SPI_CLK: length 13.5
  TOP w0.127: U11.5 19.56,13.08 19.08,12.6 13.61,12.6 9.22,16.99 R22.1
CC_SPI_CS: length 27.5
  TOP w0.127: U11.8 23.37,15.37 v1(23.42,15.42) ; v1(41.53,26.67) R46.2
  BOTTOM w0.127: v1(23.42,15.42) 23.72,15.72 35.28,15.72 41.53,21.97 v1(41.53,26.67)
CC_SPI_DIN: length 23.5
  TOP w0.127: U11.6 20.83,12.93 21.32,12.43 23.76,12.43 25.4,10.8 41.38,10.8 R65.2
CC_SPI_DOUT: length 21.8
  TOP w0.127: U11.7 22.1,13.08 22.49,12.69 23.89,12.69 25.53,11.05 42.01,11.05 R66.2
CC_UART1_CTS: length 31.7
  TOP w0.127: 14.31,19.68 v1(15.37,19.68) ; R29.1 v1(40.13,25.65)
  BOTTOM w0.127: v1(40.13,25.65) 40.13,23.24 37.72,20.83 37.71,20.83 37.55,20.68 16.89,20.68 15.9,19.68 v1(15.37,19.68)
CC_UART1_RTS: length 31.5
  TOP w0.127: v1(15.39,28.6) 15.37,28.57 U11.44 13.34,28.57 R113.2 ; v1(38.94,24.13) R36.1
  BOTTOM w0.127: v1(15.39,28.6) 26.97,28.6 29.41,26.16 36.91,26.16 v1(38.94,24.13)
CC_UART1_RX: length 2.6
  TOP w0.127: U11.47 13.98,25.1 13.54,25.1 13.06,24.61 12.57,24.61 R82.1
CC_UART1_TX: length 2.7
  TOP w0.127: R81.1 12.5,24.87 12.9,24.87 14.07,26.04 U11.46
CC_VBAT: length 64.3
  TOP w0.127: 19.43,33.02 R16.2
  TOP w0.305: v1(6.63,25.91) 6.76,26.04 R9.1
  TOP w0.762: U11.40 18.29,31.32 17.35,32.26 v1(17.35,32.66) v1(17.35,33.25) ; 18.54,33.27 18.8,33.02 ; 18.54,33.27 v1(18.54,32.72) 18.8,32.97 18.8,33.02 ; 18.54,33.27 v1(18.54,33.3) ; 18.8,33.02 20.83,33.02 22.1,31.75 22.1,31.6 ; U11.36 23.37,31.24 22.91,31.7 22.2,31.7 22.1,31.6 ; 22.1,31.6 U11.37
  TOP w1.016: R94.2 11.46,7.52 J6.1
  BOTTOM w0.127: v1(6.63,25.91) 6.73,25.91 6.78,25.86
  BOTTOM w1.016: 17.02,34.42 17.91,33.53 17.91,33.27 ; 17.02,34.42 17.02,34.16 ; 17.02,34.42 14.1,37.34 8.38,37.34 7.14,36.09 7.14,34.01 6.48,33.35 6.48,28.12 6.78,27.81 6.78,15.93 8.81,13.89 8.81,11.38 9.45,10.74 10.46,10.74 11.94,9.27 12.7,9.27 ; 17.91,33.27 17.91,33.02 17.02,33.02 17.02,34.16 ; 17.91,33.27 17.02,34.16
  vias: v1(12.32,9.52) v1(12.32,8.89) v1(12.95,9.52) v1(12.95,8.89)
CC_WL_RS232_RX: length 38.7
  TOP w0.127: v1(26.42,11.94) 26.8,11.56 40.84,11.56 R39.1 ; v1(13.41,22.23) U11.49
  BOTTOM w0.127: v1(26.42,11.94) 26.31,12.04 26.31,13.67 25.68,14.3 21.95,14.3 19.94,16.31 14.48,16.31 12.98,17.81 12.98,21.87 13.34,22.23 v1(13.41,22.23)
CC_WL_RS232_TX: length 40.7
  TOP w0.127: v1(25.78,11.89) 25.87,11.8 25.9,11.8 26.39,11.3 41.5,11.3 R40.1 ; U11.48 13.18,23.5 12.73,23.04 v1(12.73,23.01)
  BOTTOM w0.127: v1(25.78,11.89) 26.05,12.15 26.05,13.57 25.57,14.05 21.84,14.05 19.83,16.05 14.38,16.05 12.73,17.7 v1(12.73,23.01)
CC_WL_UART_TX: length 36.1
  TOP w0.127: v1(13.41,20.95) U11.50 ; R38.1 42.09,13.51 40.55,11.98 v1(29.72,11.98)
  BOTTOM w0.127: v1(29.72,11.98) 28.61,11.98 26.04,14.55 22.05,14.55 20.04,16.56 14.59,16.56 13.34,17.81 13.34,20.88 v1(13.41,20.95)
MCU_RESET: length 9.3
  TOP w0.127: R48.2 41.05,22.99 v1(41.02,23.01) ; R10.2 v1(41.02,30.1)
  BOTTOM w0.127: v1(41.02,30.1) v1(41.02,23.01)
REG_3V3: length 13.9
  TOP w0.203: C4.2 24.94,4.72 26.54,3.13 C23.2 R21.1
  TOP w0.254: U1.16 30.92,6.67 29.89,7.7 L1.2
  TOP w0.508: 23.57,7.75 22.71,7.75 J8.3 22.58,8.38 23.57,8.38
RESET_N: length 28.4
  TOP w0.127: U11.35 v1(24.64,31.6) 24.64,32.36 R210.1 ; v1(39.88,35.94) 39.88,36.85 D8.1 42.4,39.37 SW2.T2
  BOTTOM w0.127: v1(39.88,35.94) 39.17,35.23 39.17,32.58 35.16,28.57 28.68,28.57 25.98,31.27 24.97,31.27 v1(24.64,31.6)
SOP0: length 24.3
  TOP w0.127: U11.34 25.91,27.86 v1(25.86,27.81) ; J4.1 9.37,31.67 R4.1 v1(9.37,27.51)
  BOTTOM w0.127: v1(9.37,27.51) 9.75,27.89 25.78,27.89 v1(25.86,27.81)
SOP1: length 29.4
  TOP w0.127: U11.24 32.64,24.77 32.23,24.36 v1(32.23,24.31) ; v1(11.48,26.54) 11.07,26.95 R7.1 11.07,32.11 J4.3
  BOTTOM w0.127: v1(11.48,26.54) 11.61,26.67 14.96,26.67 17.12,24.51 32.03,24.51 v1(32.23,24.31)
SOP2/TCXO_EN: length 29.8
  TOP w0.127: J4.5 12.04,31.8 R8.1 11.51,28.73 v1(11.51,27.13) ; U11.23 v1(32.77,23.5)
  BOTTOM w0.127: v1(11.51,27.13) 11.63,27 15.09,27 17.3,24.79 32.44,24.79 32.77,24.46 v1(32.77,23.5)
N16764527: length 12
  TOP w0.127: J10.6 3.43,28.32 3.43,26.29 4.19,25.53 5.8,25.53 6.48,24.84 11.1,24.84 R81.2
N16764535: length 9.9
  TOP w0.127: J10.8 3.94,25.27 5.69,25.27 6.4,24.56 11.1,24.56 R82.2
N16791492: length 9.1
  TOP w0.127: R75.2 11.2,16.43 13.08,14.55 13.08,14.07 13.97,13.18 16.69,13.18 17.02,13.51 U11.3
N16793910: length 3.1
  TOP w0.127: R79.2 J3.1 29.72,33.35
  TOP w0.584: U11.31 L9.1 29.72,33.35
N16834605: length 6
  TOP w0.127: R20.2 3.77,22.9 J10.10
N16837569: length 10.8
  TOP w0.254: R9.2 8.41,32.26 9.68,33.53 J4.2 J4.4 J4.6
N16839855: length 7
  TOP w0.127: R22.2 3.78,17.81 J10.14
N16840001: length 6.2
  TOP w0.127: R24.2 8.03,12.85 3.66,12.85 J10.18
N16840004: length 6.3
  TOP w0.127: R25.2 7.82,12.57 3.68,12.57 J10.20
N16841033: length 8.3
  TOP w0.127: J9.2 46.99,33.02 46.99,31.27 46.25,30.53 44.88,30.53 43.81,29.46 R26.2
N16841054: length 3.2
  TOP w0.127: J9.4 44.09,31.75 R27.2
N16841184: length 3.2
  TOP w0.127: J9.8 43.97,26.67 R29.2
N16841224: length 2.8
  TOP w0.127: R36.2 J9.10
N16841243: length 3.6
  TOP w0.127: R37.2 44.93,19.05 J9.14
N16841270: length 4
  TOP w0.127: J9.16 43.69,14.48 R38.2
N16841340: length 3.3
  TOP w0.127: J9.18 44.07,13.97 R39.2
N16841345: length 3
  TOP w0.127: J9.20 43.36,11.43 R40.2
N16842182: length 7.3
  TOP w0.127: J9.3 46.79,30.28 45.01,30.28 42.95,28.22 R44.1
N16842199: length 6.4
  TOP w0.127: R46.1 44.2,27.91 46.96,27.91 J9.5
N16842274: length 5.9
  TOP w0.127: J9.9 47.02,22.89 43.05,22.89 R48.1
N16842295: length 18.5
  TOP w0.127: R65.1 43.03,10.21 48.97,10.21 49.83,11.07 49.83,19.43 48.26,21.01 J9.11
N16842317: length 15.6
  TOP w0.127: J9.13 49.58,17.73 49.58,11.18 48.87,10.46 43.41,10.46 R66.1
N16842351: length 6.8
  TOP w0.127: R67.1 42.98,20.09 44.93,18.14 46.63,18.14 J9.15
N16842362: length 8.7
  TOP w0.127: J9.17 47.19,15.04 47.19,17.22 46.53,17.88 44.58,17.88 43.28,19.18 R68.1
N16842381: length 10.7
  TOP w0.127: R83.1 43.59,18.26 44.22,17.63 46.41,17.63 46.91,17.12 46.91,12.78 J9.19
N16884236: length 2.4
  TOP w0.127: R10.1 40.21,33.18 D8.2
N16892431: length 1.5
  TOP w0.127: R205.2 15.32,2.13 D5.1
N16917012: length 2.2
  TOP w0.406: D3.2 41.28,7.05 ; D3.2 41.93,6.25 ; D3.2 41.28,5.45
N16970552: length 1.3
  TOP w0.254: C7.2 U1.9
N16970558: length 4.9
  TOP w0.203: C23.1 28.17,2.79 29.51,2.79 29.79,2.51 R5.2 29.97,1.98 R13.1 30.92,2.16 U1.5
N16970663: length 1.6
  TOP w0.305: 32.38,1.96 32.18,1.96 31.92,2.21 U1.7
N16970665: length 1.8
  TOP w0.305: U1.8 32.75,3.24 33.2,2.79 C3.2
N16970748: length 1.1
  TOP w0.203: R5.1 R21.2
N16976507: length 1.5
  TOP w0.127: Q7.1 9.58,2.26 R209.2
N16976519: length 1.6
  TOP w0.254: R71.1 13.72,3.96 D6.2
N16976522: length 1.7
  TOP w0.127: Q7.3 11.91,4.45 R71.2
N16976578: length 1.7
  TOP w0.127: R72.1 34.32,41.33 D1.2
N16976580: length 2
  TOP w0.127: Q8.3 36.42,41.66 R72.2
N16976712: length 24.3
  TOP w0.127: Q8.1 38.84,39.76 v1(38.84,38.94) ; R210.2 v1(25.43,31.75)
  BOTTOM w0.127: v1(38.84,38.94) 38.9,38.88 38.9,38.85 38.91,38.84 38.91,32.69 35.05,28.83 28.8,28.83 25.88,31.75 v1(25.43,31.75)
N16994679: length 1
  TOP w0.127: R76.2 J3.4 29.72,35.66
  TOP w0.584: R74.2 29.72,35.66
N16994724: length 1
  TOP w0.584: R74.1 C67.1
N16994729: length 2.3
  TOP w0.584: J2.1 L6.1 C67.2
N16994739: length 2.9
  TOP w0.406: C68.2 27.04,36.42 27.08,36.45
  TOP w0.584: R73.2 L4.1
N17016892: length 3.3
  TOP w0.584: L4.2 C64.2 arc(24.06,36.48) 23.76,36.58 arc(23.15,37.1) 22.93,37.86 ANT1.1
N17029182: length 1
  TOP w0.127: 29.72,34.82 R76.1 ; R79.1 29.72,34.16
  TOP w0.584: 29.72,34.16 29.72,34.82
N17031765: length 5.3
  TOP w0.127: SW3.T1 5.13,6.73 R12.1
N17035781: length 3.2
  TOP w0.406: R114.1 39.47,14.45 J5.1
N17040721: length 5.7
  TOP w0.127: U11.21 R112.2 37.47,20.95 TP4.1
N17042673: length 2.1
  TOP w0.406: SW2.T1 48.34,39.37 R14.1
N17042921: length 4.3
  TOP w0.127: FB18.2 43.56,8.38 45.61,6.33 J7.5
N17042983: length 8.3
  TOP w0.127: U11.12 28.45,13.84 29.64,12.65 34.87,12.65 TP2.1
N17042994: length 2.4
  TOP w0.127: TP3.1 34.59,17.14 33.7,17.14
N17043038: length 3.2
  TOP w0.127: TP5.1 35.03,22.23 U11.22

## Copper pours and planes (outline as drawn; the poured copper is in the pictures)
GND on TOP (solid shape): 24.17,41.38 23.17,41.38 23.17,37.73 22.67,37.73 22.67,41.38 20.87,41.38 20.87,42.58 24.17,42.58
GND on TOP: 1.02,0.3 0.51,0.51 0.3,1.02 0.3,42.16 0.51,42.67 1.02,42.88 18.17,42.88 18.17,42.6 18.67,42.6 18.67,41.4 18.17,41.4 18.17,37.72 24.18,37.72 24.18,42.88 49.82,42.88 50.3,42.66 50.5,42.17 50.5,1.02 50.29,0.51 49.78,0.3 ; 13 cut-outs
GND on BOTTOM: 1.02,0.3 0.51,0.51 0.3,1.02 0.3,42.16 0.51,42.67 1.02,42.88 18.17,42.88 18.17,37.72 24.18,37.72 24.18,42.88 49.79,42.88 49.82,42.87 50.29,42.66 50.5,42.18 50.5,1.02 50.29,0.51 49.78,0.3
VCC_3V3 on TOP: 16.74,3.2 16.48,3.47 16.48,3.56 16.38,3.56 16,3.94 14.48,3.94 13.34,5.08 12.06,5.08 11.81,5.33 11.81,5.97 12.19,6.35 13.72,6.35 14.61,5.46 20.04,5.46 20.79,6.22 23.09,6.22 23.47,5.83 23.47,5.09 22.86,4.49 21.78,4.49 20.5,3.2
VCC_3V3 on BOTTOM: 39.18,9.71 40.77,11.3 40.77,13.64 42.52,15.39 42.52,19.46 42.7,19.63 43.43,19.63 43.64,19.43 43.64,14.17 42.61,13.14 42.61,10.48 40.5,8.37 29.48,8.37 29.46,8.39 26.72,8.39 23.2,4.86 22.06,4.86 21.63,5.28 21.63,6.13 22.19,6.69 22.82,6.69 25.84,9.71
VCC_5V on TOP: 38.48,7.87 34.35,7.87 34.1,7.62 33.19,7.62 32.24,6.67 32.24,5.84 32.3,5.77 32.58,5.77 32.75,5.61 32.75,4.34 32.8,4.29 33.8,4.29 34.04,4.52 34.04,6.31 34.36,6.62 35.79,6.62 36.56,5.85 36.56,1.99 36.61,1.93 38.51,1.93 38.9,2.33 38.9,7.45
CC_VBAT on BOTTOM (solid shape): 18.8,33.43 18.8,32.61 18.57,32.38 16.81,32.38 16.56,32.64 16.56,33.38 16.79,33.6 18.62,33.6
CC_VBAT on TOP: 11.94,9.5 11.94,7.24 12.19,6.98 13.72,6.98 14.61,6.1 19.94,6.1 20.32,6.48 20.32,7.24 20.07,7.49 14.61,7.49 13.59,8.51 13.59,9.52 13.34,9.78 12.22,9.78
CC_VBAT on BOTTOM: 12.19,9.78 12.95,9.78 13.21,9.52 13.21,8.64 13.08,8.51 12.19,8.51 12.06,8.64 12.06,9.65
Net_48 on BOTTOM (solid shape): outline of 202 points within 188.42,91.09 192.94,95.61
Net_49 on TOP (solid shape): outline of 202 points within 193.43,91.09 197.95,95.61
Net_51 on BOTTOM (solid shape): outline of 202 points within 188.42,-7.26 192.94,-2.74
Net_52 on TOP (solid shape): outline of 202 points within 193.43,-7.26 197.95,-2.74
Net_54 on TOP (solid shape): outline of 202 points within 7.75,91.1 12.27,95.62
Net_55 on BOTTOM (solid shape): outline of 202 points within 12.75,91.1 17.27,95.62
Net_57 on TOP (solid shape): outline of 202 points within 7.75,-7.26 12.27,-2.74
Net_58 on BOTTOM (solid shape): outline of 202 points within 12.75,-7.26 17.27,-2.74
REG_3V3 on TOP: 23.48,7.08 23.21,7.35 23.21,8.4 23.43,8.62 28.47,8.62 28.69,8.39 28.69,7.19 28.58,7.08
N16888596 on TOP: 45.29,3.99 47.15,3.99 47.2,3.94 47.2,2.99 47.12,2.91 43.37,2.91 43.18,3.1 43.18,3.75 43.28,3.85 44.74,3.85 44.74,3.84 45.15,3.84
N16917012 on TOP: 40.59,7.22 40.72,7.34 43.36,7.34 44.33,6.38 44.33,4.61 44.22,4.5 43.13,4.5 42.56,5.07 40.93,5.07 40.59,5.41
N16970679 on TOP (solid shape): 29.02,5.62 30.58,5.62 30.61,5.59 30.61,4.82 30.56,4.77 29.51,4.77 29.5,4.78 29.36,4.81 29.23,4.78 29.21,4.77 28.94,4.77 28.69,4.52 26.81,4.52 26.76,4.57 26.76,5.96 26.84,6.04 28.6,6.04

Small or netless copper shapes (teardrops, artwork), in the pictures only: 1 on TOP

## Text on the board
BOTTOM: BOTTOM
Board Geometry/Soldermask Bottom: BOTTOM_SOLDERMASK
Package Geometry/Pastemask Bottom: Bottom Side Reflow | Bottom Origin
Ref Des/Silkscreen Bottom: BOTTOM_SILKSCREEN
User.Comments: 10.MATERIAL : | 11.PLATING : | 12.PCB Outline Dimension Tol: | 1. PCB VENDOR MUST BE UL  QUALIFIED | 2. BOARD MUST BE IDENTIFIED WITH APPROPRIATE VENDOR UL IDENTIFACTION MARK,DATE CODE | 3. PCB MATERIAL UL FLAMMIBILITY RATING(94V-0 MINIMUM) | 4. ALL DIMESION TOLERANCE AS BELOW UNLESS OTHERWISE SPECIFIED. | 5. PCB LAYERS : | 6. PCB THICKNESS : | 7. | 8. TOP SIDE SILKSCREEN : | 9. SOLDER MASK : | NOTES: | TRACE WIDTHS TO BE FINISHED SIZES+/-1MIL | BOTTOM SIDE SILKSCREEN: | OSP 0.2-0.6um[8-24uinch]) | HF | 2 LAYERs | FR4 | RED | 1.0 mm+/-0.1 mm | TG: | ,BOTH SIDES | WHITE | 150 | ROUTING : | CELSIUS | +/- 0.13mm | 0.8mil(min) | Core | Copper | Top(L1) | Bot(L2) | 1.8 +/-0.4 mil(H/1oz Finished) | 35.8+/-2.9 mil | (0.4~1.2 mil) | (39.37+/-4 mil) | 1.0+/-0.10 mm
TOP: TOP
Board Geometry/Soldermask Top: TOP_SOLDERMASK
Package Geometry/Pastemask Top: Top Origin | Top Side Reflow
Ref Des/Silkscreen Top: 3.3 | HIB | CLK | TX | RX | GND | 5V | VCC | PWR | MCU | ANT2 | ANT1 | NWP | CTS | RTS | WTX | IRQ | DIN | RST | CS | DO | nHIB | P1 | P3 | 0 | 1 | SOP | 2 | 95.1200 | REV.025 | 700587 | P4 | P2 | OOB(GP13) | USB PWR | CC3100MODBOOST | Rev 1.0 | TOP_SILKSCREEN
PAGE_OUTLINE: Scale 1000mil | PCB P/N | Layer name | Rev. | Texas Instruments | 307.00587 | 025
BODY_CENTER: J8 | J7 | J22 | J21 | J4 | J3
DISPLAY_TOP: 1 | 2 | 3 | 4 | 8 | 7 | 6 | 5 | U11 | Rotate 180 Angle | Bottom Side Reflow | Top Side Reflow | UNIT:MM | *Reference CNSBG Break-Away rule | Cavity_Number
MECH 11(SINGLE): UNIT:MM
User.9: 3.3 | HIB | CLK | TX | RX | GND | 5V | VCC | PWR | MCU | LDO | GP12 | OOB | ANT1 | ANT2 | NWP | CTS | RTS | WTX | IRQ | DIN | RST | CS | DO | nHIB | P1 | P3 | 0 | 1 | SOP | 2 | 2.4G | P4 | P2 | OOB(GP13) | S | K | O | I | USB PWR | CC3100BOOST | Rev 3.2
User.10: MID1(L2)
User.11: MID2(L3)
User.12: MID3(L4)
User.13: MID4(L5)
User.14: MID5(L6)
User.15: MID6(L7)
User.16: MID7(L8)
User.17: MID8(L9)
User.18: MID9(L10)
User.19: MID11(L12)
User.20: MID12(L13)
User.23: BOTTOM_PASTE
User.24: TOP_PASTE
User.27: NCDRILL
User.37: FIGURE | SIZE | 10.0 | 14.0 | 25.59 | 39.0 | 39.37 | 157.0 | 58.0x19.0 | DRILL CHART: TOP to BOTTOM | ALL UNITS ARE IN MILS | TOLERANCE | +3.0/-3.0 | +4.0/-0.0 | +4.0/-4.0 | PLATED | NON-PLATED | QTY | 596 | 4 | 6 | 40 | 7
